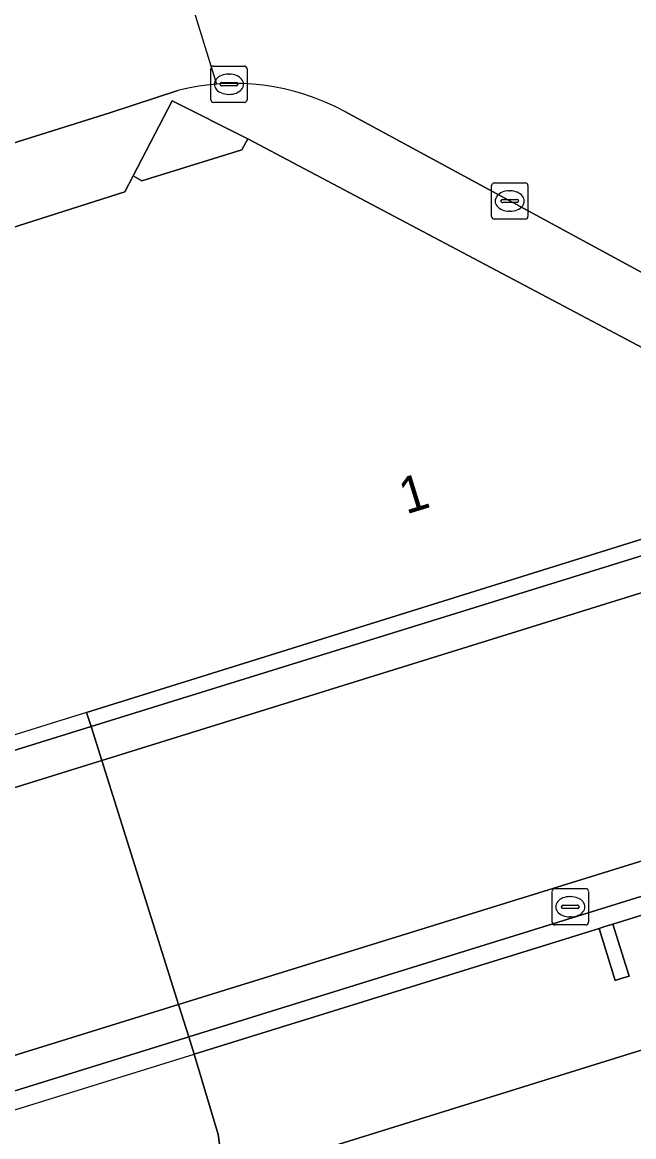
# Model space of a CAD drawing. Extents: x 160806 to 161707, y 383696 to 384148.
# Drawn here: x 161299.85 to 161316.7, y 383877.62 to 383908.31 of the extents above; entities that cross this region are included whole.
import ezdxf

# ---------------------------------------------------------------- set-up
doc = ezdxf.new("R2010")
doc.units = 0
for name, color, linetype in [('IMGEO_Dek', 7, 'Continuous'), ('IMGEO_Groenvoorziening', 7, 'Continuous'), ('IMGEO_Haag', 7, 'Continuous'), ('IMGEO_Kolk', 7, 'Continuous'), ('IMGEO_Lijnafwatering', 7, 'Continuous'), ('IMGEO_Muur', 7, 'Continuous'), ('IMGEO_OVBaan_gesloten', 7, 'Continuous'), ('IMGEO_Pand', 7, 'Continuous'), ('IMGEO_Pand_nummerreeks', 7, 'Continuous'), ('IMGEO_Pand_overbouw', 7, 'Continuous'), ('IMGEO_Rioolput', 7, 'Continuous'), ('IMGEO_Voetpad_open', 7, 'Continuous')]:
    doc.layers.add(name, color=color, linetype=linetype)

msp = doc.modelspace()

# ---------------------------------------------------------------- linework, layer by layer
at = {"layer": 'IMGEO_Dek'}
msp.add_lwpolyline([(161302.038, 383887.98), (161301.743, 383888.915), (161301.62, 383889.306), (161295.624, 383887.436), (161294.221, 383887.002), (161287.509, 383884.926), (161284.106, 383883.873), (161278.902, 383882.264), (161278.108, 383882.018), (161278.23, 383881.626), (161278.509, 383880.732), (161280.618, 383873.97), (161280.9, 383873.066), (161281.046, 383872.599), (161281.82, 383872.838), (161287.026, 383874.44), (161290.463, 383875.507), (161297.147, 383877.582), (161298.569, 383878.023), (161304.585, 383879.891), (161304.435, 383880.368), (161304.154, 383881.259)], close=True, dxfattribs=at)
at = {"layer": 'IMGEO_Groenvoorziening'}
msp.add_lwpolyline([(161316.123, 383883.472), (161315.903, 383883.404), (161315.741, 383883.354), (161316.186, 383881.921), (161316.348, 383881.972), (161316.568, 383882.04)], close=True, dxfattribs=at)
at = {"layer": 'IMGEO_Haag'}
msp.add_lwpolyline([(161316.123, 383883.472), (161315.903, 383883.404), (161315.741, 383883.354), (161316.186, 383881.921), (161316.348, 383881.972), (161316.568, 383882.04)], close=True, dxfattribs=at)
at = {"layer": 'IMGEO_Kolk'}
for p, q in [((161305.042, 383906.181), (161305.042, 383907.033)), ((161305.117, 383907.107), (161305.969, 383907.107)), ((161306.043, 383907.033), (161306.043, 383906.181)), ((161305.53, 383906.887), (161305.555, 383906.887)), ((161305.301, 383906.601), (161305.301, 383906.613)), ((161305.739, 383906.564), (161305.341, 383906.564)), ((161305.344, 383906.65), (161305.742, 383906.65)), ((161305.785, 383906.613), (161305.785, 383906.601)), ((161305.969, 383906.107), (161305.117, 383906.107)), ((161305.553, 383906.327), (161305.528, 383906.327)), ((161312.78, 383902.963), (161312.78, 383903.815)), ((161312.855, 383903.889), (161313.707, 383903.889)), ((161313.268, 383903.669), (161313.293, 383903.669)), ((161313.781, 383903.815), (161313.781, 383902.963)), ((161313.039, 383903.383), (161313.039, 383903.395)), ((161313.477, 383903.346), (161313.079, 383903.346)), ((161313.082, 383903.432), (161313.48, 383903.432)), ((161313.523, 383903.395), (161313.523, 383903.383)), ((161313.291, 383903.109), (161313.266, 383903.109)), ((161313.707, 383902.889), (161312.855, 383902.889))]:
    msp.add_line(p, q, dxfattribs=at)
for points in [[(161305.042, 383906.181), (161305.042, 383907.033)], [(161305.117, 383907.107), (161305.969, 383907.107)], [(161306.043, 383907.033), (161306.043, 383906.181)], [(161305.969, 383906.107), (161305.117, 383906.107)], [(161312.78, 383902.963), (161312.78, 383903.815)], [(161312.855, 383903.889), (161313.707, 383903.889)], [(161313.781, 383903.815), (161313.781, 383902.963)], [(161313.707, 383902.889), (161312.855, 383902.889)]]:
    msp.add_lwpolyline(points, dxfattribs=at)
for centre, radius, start, end in [((161305.119, 383907.031), 0.0765, 91.552, 178.448), ((161305.119, 383907.031), 0.0765, 91.552, 178.448), ((161305.967, 383907.031), 0.0765, 1.552, 88.448), ((161305.967, 383907.031), 0.0765, 1.552, 88.448), ((161305.341, 383906.61), 0.0403, 85.8775, 175.7526), ((161305.338, 383906.6), 0.0366, 178.938, 274.7102), ((161305.742, 383906.607), 0.043, 264.8664, 352.4533), ((161305.746, 383906.612), 0.0386, 1.7309, 96.639), ((161305.119, 383906.183), 0.0765, 181.552, 268.448), ((161305.119, 383906.183), 0.0765, 181.552, 268.448), ((161305.967, 383906.183), 0.0765, 271.552, 358.448), ((161305.967, 383906.183), 0.0765, 271.552, 358.448), ((161312.857, 383903.813), 0.0765, 91.552, 178.448), ((161312.857, 383903.813), 0.0765, 91.552, 178.448), ((161313.705, 383903.813), 0.0765, 1.552, 88.448), ((161313.705, 383903.813), 0.0765, 1.552, 88.448), ((161313.079, 383903.392), 0.0403, 85.8775, 175.7526), ((161313.076, 383903.382), 0.0366, 178.938, 274.7102), ((161313.48, 383903.389), 0.043, 264.8664, 352.4533), ((161313.484, 383903.394), 0.0386, 1.7309, 96.639), ((161312.857, 383902.965), 0.0765, 181.552, 268.448), ((161312.857, 383902.965), 0.0765, 181.552, 268.448), ((161313.705, 383902.965), 0.0765, 271.552, 358.448), ((161313.705, 383902.965), 0.0765, 271.552, 358.448)]:
    msp.add_arc(centre, radius, start, end, dxfattribs=at)
for centre, major_axis, ratio, start_param, end_param in [((161305.529, 383906.607), (-0.387, 0.002), 0.722429, 4.712389, 7.853982), ((161305.554, 383906.607), (-0.39, 0.002), 0.717154, 1.570796, 4.712389), ((161313.267, 383903.389), (-0.387, 0.002), 0.722429, 4.712389, 7.853982), ((161313.292, 383903.389), (-0.39, 0.002), 0.717154, 1.570796, 4.712389)]:
    msp.add_ellipse(centre, major_axis=major_axis, ratio=ratio, start_param=start_param, end_param=end_param, dxfattribs=at)
at = {"layer": 'IMGEO_Lijnafwatering'}
msp.add_lwpolyline([(161303.454, 383912.26), (161305.198, 383906.61)], dxfattribs=at)
at = {"layer": 'IMGEO_Muur'}
for points in [[(161301.743, 383888.915), (161347.203, 383903.006), (161347.112, 383903.36), (161321.004, 383895.352), (161301.62, 383889.306)], [(161345.376, 383892.553), (161345.53, 383892.601), (161345.382, 383893.076), (161304.435, 383880.368), (161304.585, 383879.891), (161315.741, 383883.354), (161315.903, 383883.404), (161316.123, 383883.472), (161318.72, 383884.278), (161319.007, 383884.368), (161325.28, 383886.315)], [(161287.63, 383884.54), (161294.34, 383886.62), (161295.743, 383887.055), (161301.743, 383888.915), (161301.62, 383889.306), (161295.624, 383887.436), (161294.221, 383887.002), (161287.509, 383884.926), (161284.106, 383883.873), (161278.902, 383882.264), (161278.108, 383882.018), (161278.23, 383881.626), (161279.023, 383881.872), (161284.226, 383883.485)], [(161297.147, 383877.582), (161298.569, 383878.023), (161304.585, 383879.891), (161304.435, 383880.368), (161298.419, 383878.501), (161296.998, 383878.06), (161290.313, 383875.986), (161286.877, 383874.92), (161281.672, 383873.306), (161280.9, 383873.066), (161281.046, 383872.599), (161281.82, 383872.838), (161287.026, 383874.44), (161290.463, 383875.507)]]:
    msp.add_lwpolyline(points, close=True, dxfattribs=at)
at = {"layer": 'IMGEO_OVBaan_gesloten'}
for points in [[(161295.14, 383903.591), (161302.256, 383905.822), (161304.13, 383906.433)], [(161308.732, 383905.853), (161313.367, 383903.352), (161321.12, 383899.144)], [(161346.876, 383889.332), (161346.451, 383889.201), (161331.565, 383884.581), (161326.342, 383882.967), (161326.277, 383882.947), (161320.066, 383880.988), (161307.755, 383877.154)]]:
    msp.add_lwpolyline(points, dxfattribs=at)
for points in [[(161345.176, 383893.965), (161350.423, 383895.745), (161348.388, 383901.97), (161347.434, 383902.047), (161346.273, 383901.726), (161302.038, 383887.98), (161304.154, 383881.259)], [(161304.154, 383881.259), (161302.038, 383887.98), (161296.037, 383886.115), (161294.632, 383885.679), (161287.926, 383883.595), (161284.52, 383882.537), (161280.238, 383881.206), (161279.315, 383880.927), (161278.509, 383880.732), (161280.618, 383873.97), (161281.392, 383874.209), (161286.598, 383875.822), (161290.031, 383876.885), (161296.72, 383878.957), (161298.139, 383879.396)]]:
    msp.add_lwpolyline(points, close=True, dxfattribs=at)
msp.add_arc((161305.695, 383900.303), 6.326, 61.3104, 104.3231, dxfattribs=at)
at = {"layer": 'IMGEO_Pand'}
msp.add_lwpolyline([(161305.221, 383875.707), (161305.383, 383876.689), (161305.243, 383877.676), (161304.585, 383879.891), (161304.435, 383880.368), (161304.154, 383881.259), (161302.038, 383887.98), (161301.743, 383888.915), (161301.62, 383889.306), (161321.004, 383895.352), (161321.776, 383896.787), (161306.059, 383905.099), (161305.902, 383904.803), (161303.144, 383903.945), (161302.908, 383904.083), (161302.675, 383903.641), (161297.622, 383902.04), (161297.351, 383902.908), (161296.551, 383901.496)], dxfattribs=at)
at = {"layer": 'IMGEO_Pand_overbouw'}
msp.add_lwpolyline([(161306.059, 383905.099), (161303.982, 383906.148), (161302.908, 383904.083), (161303.144, 383903.945), (161305.902, 383904.803)], close=True, dxfattribs=at)
at = {"layer": 'IMGEO_Rioolput'}
for p, q in [((161314.449, 383883.524), (161314.449, 383884.376)), ((161314.524, 383884.45), (161315.376, 383884.45)), ((161315.45, 383884.376), (161315.45, 383883.524)), ((161314.751, 383883.993), (161315.149, 383883.993)), ((161314.937, 383884.23), (161314.962, 383884.23)), ((161314.708, 383883.944), (161314.708, 383883.956)), ((161315.146, 383883.907), (161314.748, 383883.907)), ((161315.192, 383883.956), (161315.192, 383883.944)), ((161315.376, 383883.45), (161314.524, 383883.45)), ((161314.96, 383883.67), (161314.935, 383883.67))]:
    msp.add_line(p, q, dxfattribs=at)
for points in [[(161314.449, 383883.524), (161314.449, 383884.376)], [(161314.524, 383884.45), (161315.376, 383884.45)], [(161315.45, 383884.376), (161315.45, 383883.524)], [(161315.376, 383883.45), (161314.524, 383883.45)]]:
    msp.add_lwpolyline(points, dxfattribs=at)
for centre, radius, start, end in [((161314.526, 383884.374), 0.0765, 91.552, 178.448), ((161314.526, 383884.374), 0.0765, 91.552, 178.448), ((161315.374, 383884.374), 0.0765, 1.552, 88.448), ((161315.374, 383884.374), 0.0765, 1.552, 88.448), ((161314.748, 383883.953), 0.0403, 85.8775, 175.7526), ((161315.153, 383883.955), 0.0386, 1.7309, 96.639), ((161314.745, 383883.943), 0.0366, 178.938, 274.7102), ((161315.149, 383883.95), 0.043, 264.8664, 352.4533), ((161314.526, 383883.526), 0.0765, 181.552, 268.448), ((161314.526, 383883.526), 0.0765, 181.552, 268.448), ((161315.374, 383883.526), 0.0765, 271.552, 358.448), ((161315.374, 383883.526), 0.0765, 271.552, 358.448)]:
    msp.add_arc(centre, radius, start, end, dxfattribs=at)
for centre, major_axis, ratio, start_param, end_param in [((161314.936, 383883.95), (-0.387, 0.002), 0.722429, 4.712389, 7.853982), ((161314.961, 383883.95), (-0.39, 0.002), 0.717154, 1.570796, 4.712389)]:
    msp.add_ellipse(centre, major_axis=major_axis, ratio=ratio, start_param=start_param, end_param=end_param, dxfattribs=at)
at = {"layer": 'IMGEO_Voetpad_open'}
for points in [[(161304.13, 383906.433), (161302.256, 383905.822), (161295.14, 383903.591)], [(161296.551, 383901.496), (161297.351, 383902.908), (161297.622, 383902.04), (161302.675, 383903.641), (161302.908, 383904.083), (161303.982, 383906.148), (161306.059, 383905.099), (161321.776, 383896.787), (161321.004, 383895.352), (161347.112, 383903.36), (161347.203, 383903.006), (161301.743, 383888.915), (161302.038, 383887.98), (161346.273, 383901.726)], [(161321.12, 383899.144), (161313.367, 383903.352), (161308.732, 383905.853)], [(161345.514, 383894.045), (161345.176, 383893.965), (161304.154, 383881.259), (161304.435, 383880.368), (161345.382, 383893.076)], [(161307.755, 383877.154), (161320.066, 383880.988), (161326.277, 383882.947), (161326.342, 383882.967), (161331.565, 383884.581), (161346.451, 383889.201), (161346.193, 383890.004), (161331.299, 383885.447), (161326.063, 383883.845), (161319.774, 383881.921), (161319.485, 383881.831), (161318.72, 383884.278), (161316.123, 383883.472), (161316.568, 383882.04), (161316.348, 383881.972), (161316.186, 383881.921), (161315.741, 383883.354), (161304.585, 383879.891), (161305.243, 383877.676), (161305.383, 383876.689)]]:
    msp.add_lwpolyline(points, dxfattribs=at)
for points in [[(161306.059, 383905.099), (161303.982, 383906.148), (161302.908, 383904.083), (161303.144, 383903.945), (161305.902, 383904.803)], [(161294.632, 383885.679), (161296.037, 383886.115), (161302.038, 383887.98), (161301.743, 383888.915), (161295.743, 383887.055), (161294.34, 383886.62), (161287.63, 383884.54), (161284.226, 383883.485), (161279.023, 383881.872), (161278.23, 383881.626), (161278.509, 383880.732), (161279.315, 383880.927), (161280.238, 383881.206), (161284.52, 383882.537), (161287.926, 383883.595)], [(161296.998, 383878.06), (161298.419, 383878.501), (161304.435, 383880.368), (161304.154, 383881.259), (161298.139, 383879.396), (161296.72, 383878.957), (161290.031, 383876.885), (161286.598, 383875.822), (161281.392, 383874.209), (161280.618, 383873.97), (161280.9, 383873.066), (161281.672, 383873.306), (161286.877, 383874.92), (161290.313, 383875.986)]]:
    msp.add_lwpolyline(points, close=True, dxfattribs=at)
msp.add_arc((161305.695, 383900.303), 6.326, 61.3104, 104.3231, dxfattribs=at)

# ---------------------------------------------------------------- texts
at = {"layer": 'IMGEO_Pand_nummerreeks'}
msp.add_text('1', height=1, rotation=17.1713, dxfattribs=at).set_placement((161310.424, 383894.753))

doc.saveas('drawing.dxf')
